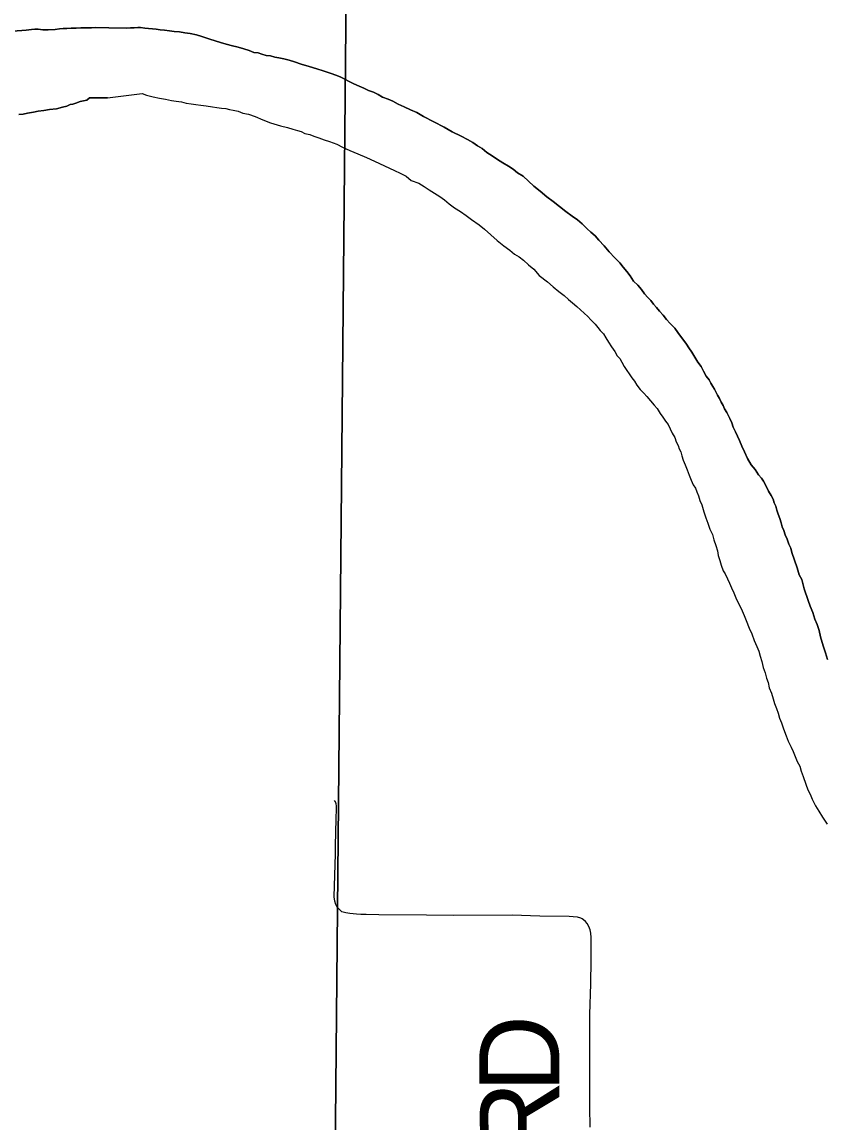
# Model space of a CAD drawing. Extents: x 2.4 to 73.1, y 4.5 to 25.6.
# Drawn here: x 32.412 to 32.6973, y 22.7265 to 23.1171 of the extents above; entities that cross this region are included whole.
import ezdxf

# ---------------------------------------------------------------- set-up
doc = ezdxf.new("R2010")
doc.units = 0
for name, color, linetype in [('GM_X_Major_River', 7, 'Continuous'), ('GM_X_Section', 7, 'Continuous'), ('GM_X_Township_Road', 7, 'Continuous'), ('GM_X_Township_Road_Text', 7, 'Continuous')]:
    doc.layers.add(name, color=color, linetype=linetype)

msp = doc.modelspace()

# ---------------------------------------------------------------- linework, layer by layer
at = {"layer": 'GM_X_Major_River'}
for points in [[(32.41942, 23.11433), (32.41771, 23.11455), (32.41657, 23.11456), (32.41543, 23.11439), (32.41352, 23.11423), (32.40553, 23.1136)], [(32.40553, 23.1136), (32.41352, 23.11423), (32.41543, 23.11439), (32.41657, 23.11456), (32.41771, 23.11455), (32.41942, 23.11433)], [(32.44289, 23.11499), (32.43807, 23.11517), (32.43674, 23.115), (32.43484, 23.11503), (32.43294, 23.11506), (32.43122, 23.1149), (32.42951, 23.11493), (32.42799, 23.11476), (32.42666, 23.11478), (32.42532, 23.11461), (32.4238, 23.11445), (32.42132, 23.1143), (32.42037, 23.11431), (32.41942, 23.11433)], [(32.41942, 23.11433), (32.42037, 23.11431), (32.42132, 23.1143), (32.4238, 23.11445), (32.42532, 23.11461), (32.42666, 23.11478), (32.42799, 23.11476), (32.42951, 23.11493), (32.43122, 23.1149), (32.43294, 23.11506), (32.43484, 23.11503), (32.43674, 23.115), (32.43807, 23.11517), (32.44289, 23.11499)], [(32.63514, 23.01825), (32.63402, 23.01923), (32.63292, 23.02059), (32.63182, 23.02213), (32.63052, 23.02369), (32.62904, 23.02505), (32.62776, 23.02698), (32.62666, 23.02853), (32.62537, 23.03008), (32.62408, 23.03163), (32.62241, 23.03339), (32.62037, 23.03552), (32.61853, 23.03766), (32.61668, 23.03961), (32.61539, 23.04116), (32.6139, 23.04252), (32.6126, 23.0437), (32.61075, 23.04545), (32.60907, 23.04682), (32.60721, 23.0482), (32.60497, 23.04978), (32.60273, 23.05154), (32.6005, 23.05331), (32.59826, 23.05507), (32.59584, 23.05703), (32.59361, 23.0588), (32.59175, 23.06056), (32.5899, 23.06231), (32.58784, 23.0635), (32.58635, 23.06487), (32.58467, 23.06586), (32.58261, 23.06705), (32.58074, 23.06824), (32.57887, 23.06962), (32.577, 23.0708), (32.57533, 23.07217), (32.57364, 23.07317), (32.57197, 23.07435), (32.57009, 23.07534), (32.56784, 23.07654), (32.56465, 23.07814), (32.56184, 23.07973), (32.55453, 23.08352), (32.5521, 23.08491), (32.54984, 23.08592), (32.54759, 23.08693), (32.54553, 23.08793), (32.54365, 23.08893), (32.54196, 23.08973), (32.53989, 23.09035), (32.53839, 23.09134), (32.5367, 23.09214), (32.53501, 23.09275), (32.53332, 23.09356), (32.53163, 23.09436), (32.52975, 23.09516), (32.52806, 23.09597), (32.52656, 23.09676), (32.52487, 23.09757), (32.52337, 23.09817), (32.52168, 23.09879), (32.51885, 23.09981), (32.51659, 23.10043), (32.51395, 23.10126), (32.51112, 23.10209), (32.50867, 23.10291), (32.50679, 23.10353), (32.5049, 23.10396), (32.5032, 23.10438), (32.50169, 23.10461), (32.50018, 23.10503), (32.49867, 23.10525), (32.49716, 23.10567), (32.49584, 23.10609), (32.49432, 23.10631), (32.49263, 23.10693), (32.49075, 23.10754), (32.48867, 23.10817), (32.48622, 23.1088), (32.48358, 23.10943), (32.48094, 23.11026), (32.4783, 23.11109), (32.47585, 23.11191), (32.47397, 23.11252), (32.4717, 23.11296), (32.46981, 23.1132), (32.46792, 23.11363), (32.46602, 23.11368), (32.46432, 23.11391), (32.46261, 23.11414), (32.4611, 23.11437), (32.45958, 23.1146), (32.4556, 23.11489), (32.45409, 23.11512), (32.45314, 23.11514), (32.45181, 23.11498), (32.45048, 23.11502), (32.44896, 23.11487), (32.44289, 23.11499)], [(32.44289, 23.11499), (32.44896, 23.11487), (32.45048, 23.11502), (32.45181, 23.11498), (32.45314, 23.11514), (32.45409, 23.11512), (32.4556, 23.11489), (32.45958, 23.1146), (32.4611, 23.11437), (32.46261, 23.11414), (32.46432, 23.11391), (32.46602, 23.11368), (32.46792, 23.11363), (32.46981, 23.1132), (32.4717, 23.11296), (32.47397, 23.11252), (32.47585, 23.11191), (32.4783, 23.11109), (32.48094, 23.11026), (32.48358, 23.10943), (32.48622, 23.1088), (32.48867, 23.10817), (32.49075, 23.10754), (32.49263, 23.10693), (32.49432, 23.10631), (32.49584, 23.10609), (32.49716, 23.10567), (32.49867, 23.10525), (32.50018, 23.10503), (32.50169, 23.10461), (32.5032, 23.10438), (32.5049, 23.10396), (32.50679, 23.10353), (32.50867, 23.10291), (32.51112, 23.10209), (32.51395, 23.10126), (32.51659, 23.10043), (32.51885, 23.09981), (32.52168, 23.09879), (32.52337, 23.09817), (32.52487, 23.09757), (32.52656, 23.09676), (32.52806, 23.09597), (32.52975, 23.09516), (32.53163, 23.09436), (32.53332, 23.09356), (32.53501, 23.09275), (32.5367, 23.09214), (32.53839, 23.09134), (32.53989, 23.09035), (32.54196, 23.08973), (32.54365, 23.08893), (32.54553, 23.08793), (32.54759, 23.08693), (32.54984, 23.08592), (32.5521, 23.08491), (32.55453, 23.08352), (32.56184, 23.07973), (32.56465, 23.07814), (32.56784, 23.07654), (32.57009, 23.07534), (32.57197, 23.07435), (32.57364, 23.07317), (32.57533, 23.07217), (32.577, 23.0708), (32.57887, 23.06962), (32.58074, 23.06824), (32.58261, 23.06705), (32.58467, 23.06586), (32.58635, 23.06487), (32.58784, 23.0635), (32.5899, 23.06231), (32.59175, 23.06056), (32.59361, 23.0588), (32.59584, 23.05703), (32.59826, 23.05507), (32.6005, 23.05331), (32.60273, 23.05154), (32.60497, 23.04978), (32.60721, 23.0482), (32.60907, 23.04682), (32.61075, 23.04545), (32.6126, 23.0437), (32.6139, 23.04252), (32.61539, 23.04116), (32.61668, 23.03961), (32.61853, 23.03766), (32.62037, 23.03552), (32.62241, 23.03339), (32.62408, 23.03163), (32.62537, 23.03008), (32.62666, 23.02853), (32.62776, 23.02698), (32.62904, 23.02505), (32.63052, 23.02369), (32.63182, 23.02213), (32.63292, 23.02059), (32.63402, 23.01923), (32.63514, 23.01825)], [(32.44232, 23.0902), (32.45464, 23.09175), (32.45615, 23.09114), (32.4586, 23.09051), (32.46087, 23.09007), (32.46295, 23.08964), (32.46503, 23.08921), (32.46673, 23.08897), (32.46862, 23.08874), (32.47032, 23.08831), (32.47203, 23.08808), (32.47373, 23.08785), (32.47543, 23.08761), (32.47733, 23.08738), (32.47959, 23.08694), (32.48111, 23.08671), (32.48281, 23.08648), (32.48433, 23.08644), (32.48565, 23.08603), (32.48697, 23.0858), (32.48867, 23.08538), (32.49036, 23.08477), (32.49244, 23.08434), (32.4947, 23.08352), (32.49752, 23.08231), (32.50016, 23.08129), (32.50374, 23.08025), (32.50619, 23.07962), (32.50807, 23.079), (32.50977, 23.07858), (32.51109, 23.07817), (32.51241, 23.07756), (32.51411, 23.07714), (32.51561, 23.07653), (32.5173, 23.07592), (32.51919, 23.0753), (32.52107, 23.07469), (32.52371, 23.07367), (32.52577, 23.07267), (32.5284, 23.07146), (32.53122, 23.07025), (32.53423, 23.06904), (32.53704, 23.06764), (32.54418, 23.06442), (32.54624, 23.06342), (32.5483, 23.06241), (32.55016, 23.06085), (32.5528, 23.05983), (32.55467, 23.05865), (32.55654, 23.05746), (32.55841, 23.05627), (32.56028, 23.05509), (32.56196, 23.0539), (32.56363, 23.05253), (32.5655, 23.05116), (32.56755, 23.04977), (32.5696, 23.04839), (32.57147, 23.04702), (32.57427, 23.04505), (32.57613, 23.04348), (32.57836, 23.04153), (32.58059, 23.03957), (32.58301, 23.03761), (32.58506, 23.03604), (32.58673, 23.03467), (32.58842, 23.03368), (32.58991, 23.0325), (32.59177, 23.03093), (32.59363, 23.02937), (32.59547, 23.02704), (32.59846, 23.02488), (32.6005, 23.02312), (32.60255, 23.02136), (32.60441, 23.01998), (32.6059, 23.01861), (32.60739, 23.01744), (32.60887, 23.01607), (32.61017, 23.0149), (32.61147, 23.01372), (32.61277, 23.01255), (32.61388, 23.01138), (32.61536, 23.00983), (32.61628, 23.00866), (32.6172, 23.0075), (32.61831, 23.00633), (32.61923, 23.00498), (32.62014, 23.00344), (32.62124, 23.0017), (32.62234, 23.00016), (32.62325, 22.99861), (32.62417, 22.99764)], [(32.44232, 23.0902), (32.45464, 23.09175), (32.45615, 23.09114), (32.4586, 23.09051), (32.46087, 23.09007), (32.46295, 23.08964), (32.46503, 23.08921), (32.46673, 23.08897), (32.46862, 23.08874), (32.47032, 23.08831), (32.47203, 23.08808), (32.47373, 23.08785), (32.47543, 23.08761), (32.47733, 23.08738), (32.47959, 23.08694), (32.48111, 23.08671), (32.48281, 23.08648), (32.48433, 23.08644), (32.48565, 23.08603), (32.48697, 23.0858), (32.48867, 23.08538), (32.49036, 23.08477), (32.49244, 23.08434), (32.4947, 23.08352), (32.49752, 23.08231), (32.50016, 23.08129), (32.50374, 23.08025), (32.50619, 23.07962), (32.50807, 23.079), (32.50977, 23.07858), (32.51109, 23.07817), (32.51241, 23.07756), (32.51411, 23.07714), (32.51561, 23.07653), (32.5173, 23.07592), (32.51919, 23.0753), (32.52107, 23.07469), (32.52371, 23.07367), (32.52577, 23.07267), (32.5284, 23.07146), (32.53122, 23.07025), (32.53423, 23.06904), (32.53704, 23.06764), (32.54418, 23.06442), (32.54624, 23.06342), (32.5483, 23.06241), (32.55016, 23.06085), (32.5528, 23.05983), (32.55467, 23.05865), (32.55654, 23.05746), (32.55841, 23.05627), (32.56028, 23.05509), (32.56196, 23.0539), (32.56363, 23.05253), (32.5655, 23.05116), (32.56755, 23.04977), (32.5696, 23.04839), (32.57147, 23.04702), (32.57427, 23.04505), (32.57613, 23.04348), (32.57836, 23.04153), (32.58059, 23.03957), (32.58301, 23.03761), (32.58506, 23.03604), (32.58673, 23.03467), (32.58842, 23.03368), (32.58991, 23.0325), (32.59177, 23.03093), (32.59363, 23.02937), (32.59547, 23.02704), (32.59846, 23.02488), (32.6005, 23.02312), (32.60255, 23.02136), (32.60441, 23.01998), (32.6059, 23.01861), (32.60739, 23.01744), (32.60887, 23.01607), (32.61017, 23.0149), (32.61147, 23.01372), (32.61277, 23.01255), (32.61388, 23.01138), (32.61536, 23.00983), (32.61628, 23.00866), (32.6172, 23.0075), (32.61831, 23.00633), (32.61923, 23.00498), (32.62014, 23.00344), (32.62124, 23.0017), (32.62234, 23.00016), (32.62325, 22.99861), (32.62417, 22.99764)], [(32.41096, 23.08426), (32.41248, 23.08442), (32.41401, 23.08478), (32.41611, 23.08512), (32.41782, 23.08548), (32.41973, 23.08564), (32.42182, 23.08598), (32.4243, 23.08632), (32.4264, 23.08686), (32.42793, 23.08722), (32.42908, 23.08777), (32.43003, 23.08794), (32.43118, 23.08831), (32.43271, 23.08885), (32.435, 23.08938), (32.43596, 23.09013), (32.44232, 23.0902)], [(32.44232, 23.0902), (32.43596, 23.09013), (32.435, 23.08938), (32.43271, 23.08885), (32.43118, 23.08831), (32.43003, 23.08794), (32.42908, 23.08777), (32.42793, 23.08722), (32.4264, 23.08686), (32.4243, 23.08632), (32.42182, 23.08598), (32.41973, 23.08564), (32.41782, 23.08548), (32.41611, 23.08512), (32.41401, 23.08478), (32.41248, 23.08442), (32.41096, 23.08426)], [(32.69785, 22.89077), (32.69715, 22.89306), (32.69626, 22.89555), (32.69539, 22.8988), (32.69488, 22.90109), (32.69417, 22.9032), (32.69327, 22.90512), (32.69257, 22.90742), (32.69168, 22.90972), (32.69097, 22.91164), (32.68955, 22.91585), (32.68868, 22.9191), (32.68778, 22.92083), (32.68708, 22.92332), (32.68512, 22.92869), (32.68478, 22.93022), (32.68406, 22.93175), (32.68353, 22.93347), (32.68281, 22.93501), (32.68228, 22.93654), (32.68175, 22.93789), (32.6814, 22.93923), (32.68087, 22.94076), (32.68034, 22.94229), (32.67981, 22.94382), (32.67946, 22.94516), (32.67892, 22.94631), (32.67857, 22.94765), (32.67785, 22.949), (32.67693, 22.95054), (32.67603, 22.95227), (32.67512, 22.95401), (32.67439, 22.95516), (32.67328, 22.95633), (32.67219, 22.95826), (32.67071, 22.95981), (32.66944, 22.96213), (32.66836, 22.96443), (32.66746, 22.96654), (32.66656, 22.96847), (32.66584, 22.97), (32.66512, 22.97154), (32.6644, 22.97327), (32.66387, 22.9748), (32.66315, 22.97634), (32.66206, 22.97845), (32.66133, 22.9798), (32.66079, 22.98095), (32.66006, 22.98211), (32.65953, 22.98345), (32.6588, 22.98461), (32.65825, 22.98577), (32.65771, 22.98673), (32.65716, 22.98769), (32.65643, 22.98885), (32.65589, 22.99), (32.65478, 22.99136), (32.65388, 22.99309), (32.65297, 22.99482), (32.65187, 22.99637), (32.65078, 22.99811), (32.64968, 22.99984), (32.64858, 23.00139), (32.64785, 23.00274), (32.64473, 23.00681), (32.64363, 23.00835), (32.64196, 23.0101), (32.64066, 23.01147), (32.63956, 23.01301), (32.63827, 23.01438), (32.63716, 23.01573), (32.63605, 23.0169), (32.63514, 23.01825)], [(32.63514, 23.01825), (32.63605, 23.0169), (32.63716, 23.01573), (32.63827, 23.01438), (32.63956, 23.01301), (32.64066, 23.01147), (32.64196, 23.0101), (32.64363, 23.00835), (32.64473, 23.00681), (32.64785, 23.00274), (32.64858, 23.00139), (32.64968, 22.99984), (32.65078, 22.99811), (32.65187, 22.99637), (32.65297, 22.99482), (32.65388, 22.99309), (32.65478, 22.99136), (32.65589, 22.99), (32.65643, 22.98885), (32.65716, 22.98769), (32.65771, 22.98673), (32.65825, 22.98577), (32.6588, 22.98461), (32.65953, 22.98345), (32.66006, 22.98211), (32.66079, 22.98095), (32.66133, 22.9798), (32.66206, 22.97845), (32.66315, 22.97634), (32.66387, 22.9748), (32.6644, 22.97327), (32.66512, 22.97154), (32.66584, 22.97), (32.66656, 22.96847), (32.66746, 22.96654), (32.66836, 22.96443), (32.66944, 22.96213), (32.67071, 22.95981), (32.67219, 22.95826), (32.67328, 22.95633), (32.67439, 22.95516), (32.67512, 22.95401), (32.67603, 22.95227), (32.67693, 22.95054), (32.67785, 22.949), (32.67857, 22.94765), (32.67892, 22.94631), (32.67946, 22.94516), (32.67981, 22.94382), (32.68034, 22.94229), (32.68087, 22.94076), (32.6814, 22.93923), (32.68175, 22.93789), (32.68228, 22.93654), (32.68281, 22.93501), (32.68353, 22.93347), (32.68406, 22.93175), (32.68478, 22.93022), (32.68512, 22.92869), (32.68708, 22.92332), (32.68778, 22.92083), (32.68868, 22.9191), (32.68955, 22.91585), (32.69097, 22.91164), (32.69168, 22.90972), (32.69257, 22.90742), (32.69327, 22.90512), (32.69417, 22.9032), (32.69488, 22.90109), (32.69539, 22.8988), (32.69626, 22.89555), (32.69715, 22.89306), (32.69785, 22.89077)], [(32.62417, 22.99764), (32.6249, 22.99629), (32.62562, 22.99476), (32.62837, 22.9907), (32.62929, 22.98954), (32.6302, 22.98818), (32.63131, 22.98664), (32.6326, 22.98527), (32.63371, 22.98411), (32.635, 22.98256), (32.63629, 22.981), (32.6374, 22.97984), (32.6385, 22.9781), (32.63941, 22.97675), (32.64033, 22.9754), (32.64125, 22.97423), (32.64197, 22.9727), (32.64269, 22.97116), (32.6436, 22.96962), (32.64414, 22.96808), (32.64486, 22.96674), (32.64521, 22.96559), (32.64575, 22.96443), (32.6461, 22.9631), (32.64663, 22.96156), (32.64735, 22.95984), (32.64806, 22.95811), (32.64878, 22.95619), (32.64949, 22.95446), (32.65021, 22.95274), (32.65094, 22.95158), (32.65148, 22.95024), (32.65201, 22.94889), (32.65254, 22.94717), (32.65326, 22.94563), (32.65396, 22.94315), (32.65467, 22.94104), (32.65538, 22.93913), (32.65608, 22.93702), (32.65698, 22.9351), (32.65751, 22.93318), (32.65822, 22.93127), (32.65874, 22.92935), (32.65908, 22.92764), (32.6596, 22.92591), (32.66013, 22.92419), (32.66084, 22.92228), (32.66157, 22.92112), (32.66229, 22.91939), (32.66301, 22.91785), (32.66373, 22.91613), (32.66463, 22.91439), (32.66535, 22.91267), (32.66751, 22.90805), (32.66823, 22.90633), (32.66895, 22.9046), (32.67002, 22.90191), (32.67092, 22.8998), (32.67181, 22.8975), (32.67271, 22.89539), (32.67342, 22.89366), (32.67395, 22.89194), (32.67447, 22.89003), (32.67499, 22.88793), (32.6757, 22.88601), (32.67622, 22.8841), (32.67675, 22.88256), (32.67708, 22.88066), (32.67799, 22.87873), (32.67851, 22.87682), (32.67903, 22.8751), (32.67975, 22.87337), (32.68028, 22.87165), (32.6808, 22.86993), (32.68152, 22.8682), (32.68205, 22.86648), (32.68258, 22.86514), (32.68312, 22.8636), (32.68383, 22.86169), (32.68491, 22.85957), (32.68564, 22.85803), (32.68635, 22.85631), (32.68707, 22.85458), (32.68797, 22.85284), (32.6885, 22.85112), (32.68921, 22.84921), (32.6901, 22.84652), (32.6908, 22.84442), (32.69171, 22.84288), (32.69243, 22.84115), (32.69351, 22.83884), (32.69479, 22.83691), (32.69607, 22.83479), (32.69772, 22.83228)], [(32.62417, 22.99764), (32.6249, 22.99629), (32.62562, 22.99476), (32.62837, 22.9907), (32.62929, 22.98954), (32.6302, 22.98818), (32.63131, 22.98664), (32.6326, 22.98527), (32.63371, 22.98411), (32.635, 22.98256), (32.63629, 22.981), (32.6374, 22.97984), (32.6385, 22.9781), (32.63941, 22.97675), (32.64033, 22.9754), (32.64125, 22.97423), (32.64197, 22.9727), (32.64269, 22.97116), (32.6436, 22.96962), (32.64414, 22.96808), (32.64486, 22.96674), (32.64521, 22.96559), (32.64575, 22.96443), (32.6461, 22.9631), (32.64663, 22.96156), (32.64735, 22.95984), (32.64806, 22.95811), (32.64878, 22.95619), (32.64949, 22.95446), (32.65021, 22.95274), (32.65094, 22.95158), (32.65148, 22.95024), (32.65201, 22.94889), (32.65254, 22.94717), (32.65326, 22.94563), (32.65396, 22.94315), (32.65467, 22.94104), (32.65538, 22.93913), (32.65608, 22.93702), (32.65698, 22.9351), (32.65751, 22.93318), (32.65822, 22.93127), (32.65874, 22.92935), (32.65908, 22.92764), (32.6596, 22.92591), (32.66013, 22.92419), (32.66084, 22.92228), (32.66157, 22.92112), (32.66229, 22.91939), (32.66301, 22.91785), (32.66373, 22.91613), (32.66463, 22.91439), (32.66535, 22.91267), (32.66751, 22.90805), (32.66823, 22.90633), (32.66895, 22.9046), (32.67002, 22.90191), (32.67092, 22.8998), (32.67181, 22.8975), (32.67271, 22.89539), (32.67342, 22.89366), (32.67395, 22.89194), (32.67447, 22.89003), (32.67499, 22.88793), (32.6757, 22.88601), (32.67622, 22.8841), (32.67675, 22.88256), (32.67708, 22.88066), (32.67799, 22.87873), (32.67851, 22.87682), (32.67903, 22.8751), (32.67975, 22.87337), (32.68028, 22.87165), (32.6808, 22.86993), (32.68152, 22.8682), (32.68205, 22.86648), (32.68258, 22.86514), (32.68312, 22.8636), (32.68383, 22.86169), (32.68491, 22.85957), (32.68564, 22.85803), (32.68635, 22.85631), (32.68707, 22.85458), (32.68797, 22.85284), (32.6885, 22.85112), (32.68921, 22.84921), (32.6901, 22.84652), (32.6908, 22.84442), (32.69171, 22.84288), (32.69243, 22.84115), (32.69351, 22.83884), (32.69479, 22.83691), (32.69607, 22.83479), (32.69772, 22.83228)]]:
    msp.add_lwpolyline(points, dxfattribs=at)
at = {"layer": 'GM_X_Section'}
for points in [[(32.52707, 23.1282), (32.52237, 22.62648), (32.0257, 22.62946), (32.03128, 23.13003)], [(33.03536, 23.12164), (33.02904, 22.62432), (32.52237, 22.62648), (32.52707, 23.1282)]]:
    msp.add_lwpolyline(points, close=True, dxfattribs=at)
at = {"layer": 'GM_X_Township_Road'}
msp.add_lwpolyline([(32.61364, 22.72473), (32.61351, 22.73181), (32.6135, 22.76469), (32.61384, 22.77557), (32.61391, 22.78395), (32.61402, 22.7886), (32.614, 22.79203), (32.61385, 22.79357), (32.61359, 22.79479), (32.61315, 22.79595), (32.61253, 22.79702), (32.61193, 22.79774), (32.61125, 22.79835), (32.61077, 22.79865), (32.61027, 22.79888), (32.60914, 22.79925), (32.6076, 22.7994), (32.60622, 22.79945), (32.59573, 22.79959), (32.58589, 22.79991), (32.56523, 22.79982), (32.55551, 22.79999), (32.53867, 22.8001), (32.53415, 22.80015), (32.53221, 22.80025), (32.53074, 22.80035), (32.52837, 22.80055), (32.52689, 22.8008), (32.52553, 22.80118), (32.52443, 22.80223), (32.52385, 22.80285), (32.52335, 22.80376), (32.52299, 22.80493), (32.52284, 22.80645), (32.52321, 22.8217), (32.5233, 22.82461), (32.52351, 22.83415), (32.52361, 22.83776), (32.52357, 22.83873), (32.52347, 22.83945), (32.5232, 22.84019), (32.52287, 22.84067)], dxfattribs=at)

# ---------------------------------------------------------------- texts
at = {"layer": 'GM_X_Township_Road_Text'}
for s, rotation, p in [('D', 90.0419, (32.60267, 22.73705)), ('R', 91.0168, (32.60308, 22.71384))]:
    msp.add_text(s, height=0.02841, rotation=rotation, dxfattribs=at).set_placement(p)

doc.saveas('drawing.dxf')
